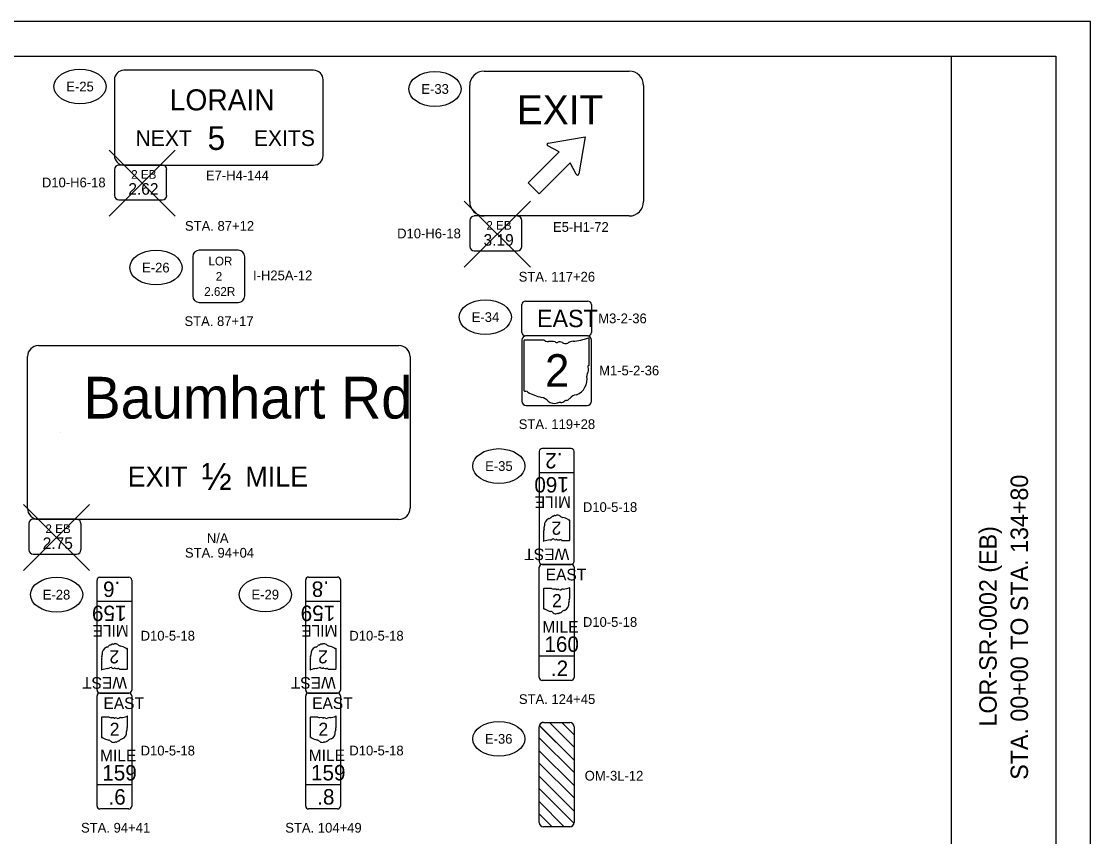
# Model space of a CAD drawing. Extents: x 0 to 34, y 0 to 22.
# Drawn here: x 18.63 to 34, y 10.28 to 22 of the extents above; entities that cross this region are included whole.
import ezdxf

# ---------------------------------------------------------------- set-up
doc = ezdxf.new("R2010")
doc.units = 0
for name, color, linetype in [('SH_Border', 7, 'Continuous'), ('SH_Cut_Line', 7, 'Continuous'), ('SH_Data', 7, 'Continuous'), ('SH_Text', 7, 'Continuous'), ('SN_P_Signs', 7, 'Continuous'), ('SN_X_Public', 7, 'Continuous')]:
    doc.layers.add(name, color=color, linetype=linetype)

msp = doc.modelspace()

# ---------------------------------------------------------------- linework, layer by layer
at = {"layer": 'SH_Border'}
msp.add_line((32, 0.5), (32, 21.5), dxfattribs=at)
msp.add_lwpolyline([(1.5, 21.5), (33.5, 21.5), (33.5, 0.5), (1.5, 0.5)], close=True, dxfattribs=at)
at = {"layer": 'SH_Cut_Line'}
msp.add_lwpolyline([(0, 0), (34, 0), (34, 22), (0, 22)], close=True, dxfattribs=at)
at = {"layer": 'SH_Text'}
for points in [[(18.878, 17.34), (24.058, 17.34)], [(18.718, 15), (18.718, 17.18)], [(24.218, 17.18), (24.218, 15)], [(26.533, 15.859), (26.117, 15.859)], [(26.075, 15.817), (26.075, 14.234)], [(26.575, 14.234), (26.575, 15.817)], [(24.058, 14.84), (18.878, 14.84)], [(26.075, 12.567), (26.075, 14.151)], [(26.117, 14.192), (26.533, 14.192)], [(26.117, 14.192), (26.533, 14.192)], [(26.575, 14.151), (26.575, 12.567)], [(26.533, 12.526), (26.117, 12.526)]]:
    msp.add_lwpolyline(points, dxfattribs=at)
for centre, radius, start, end in [((18.878, 17.18), 0.16, 90, 180), ((24.058, 17.18), 0.16, 0, 90), ((26.117, 15.817), 0.0417, 90, 180), ((26.533, 15.817), 0.0417, 0, 90), ((18.878, 15), 0.16, 180, 270), ((24.058, 15), 0.16, 270, 0), ((26.117, 14.234), 0.0417, 180, 270), ((26.117, 14.151), 0.0417, 90, 180), ((26.533, 14.234), 0.0417, 270, 360), ((26.533, 14.151), 0.0417, 0, 90), ((26.117, 12.567), 0.0417, 180, 270), ((26.533, 12.567), 0.0417, 270, 0)]:
    msp.add_arc(centre, radius, start, end, dxfattribs=at)
for centre in [(19.473, 21.063), (24.575, 21.028), (20.565, 18.46), (25.299, 17.748), (25.494, 15.607), (19.137, 13.758), (22.137, 13.759), (25.494, 11.685)]:
    msp.add_ellipse(centre, major_axis=(0.375, 0), ratio=0.666667, dxfattribs=at)
at = {"layer": 'SN_P_Signs'}
for p, q in [((26.202, 20.25), (26.733, 20.34)), ((26.36, 20.124), (26.196, 20.21)), ((25.916, 19.679), (26.36, 20.124)), ((26.518, 19.967), (26.073, 19.522)), ((26.604, 19.802), (26.518, 19.967)), ((26.073, 19.522), (25.916, 19.679)), ((26.605, 19.802), (26.604, 19.802)), ((25.825, 17.529), (25.825, 17.929)), ((25.875, 17.979), (26.775, 17.979)), ((26.825, 17.929), (26.825, 17.529)), ((25.855, 17.407), (25.855, 16.695)), ((26.139, 17.419), (25.865, 17.419)), ((26.775, 17.479), (25.875, 17.479)), ((26.793, 17.065), (26.793, 17.437)), ((26.793, 17.065), (26.793, 17.065)), ((19.199, 16.09), (19.199, 16.09)), ((26.075, 15.512), (26.575, 15.512)), ((26.512, 14.542), (26.512, 14.827)), ((26.137, 14.679), (26.137, 14.53)), ((26.137, 14.679), (26.137, 14.679)), ((26.325, 14.713), (26.325, 14.713)), ((26.399, 14.537), (26.509, 14.537)), ((26.137, 13.842), (26.137, 13.558)), ((26.251, 13.847), (26.141, 13.847)), ((26.512, 13.705), (26.512, 13.854)), ((26.512, 13.705), (26.512, 13.705)), ((19.718, 13.663), (20.218, 13.663)), ((22.718, 13.663), (23.218, 13.663)), ((26.325, 13.671), (26.325, 13.671)), ((20.156, 12.693), (20.156, 12.978)), ((23.156, 12.694), (23.156, 12.978)), ((19.781, 12.83), (19.781, 12.681)), ((19.781, 12.83), (19.781, 12.83)), ((19.968, 12.864), (19.968, 12.864)), ((22.781, 12.831), (22.781, 12.682)), ((22.781, 12.831), (22.781, 12.831)), ((22.968, 12.865), (22.968, 12.865)), ((26.575, 12.873), (26.075, 12.873)), ((20.042, 12.688), (20.152, 12.688)), ((23.042, 12.689), (23.152, 12.689)), ((19.781, 11.993), (19.781, 11.709)), ((19.894, 11.998), (19.784, 11.998)), ((20.156, 11.856), (20.156, 12.005)), ((22.781, 11.994), (22.781, 11.709)), ((22.894, 11.999), (22.784, 11.999)), ((23.156, 11.857), (23.156, 12.006)), ((20.156, 11.856), (20.156, 11.856)), ((23.156, 11.857), (23.156, 11.857)), ((26.575, 11.378), (26.075, 11.878)), ((26.575, 11.567), (26.22, 11.922)), ((26.575, 11.744), (26.397, 11.922)), ((19.968, 11.822), (19.968, 11.822)), ((22.968, 11.823), (22.968, 11.823)), ((26.575, 11.201), (26.075, 11.701)), ((26.575, 11.013), (26.075, 11.513)), ((26.575, 10.836), (26.075, 11.336)), ((26.575, 10.647), (26.075, 11.147)), ((20.218, 11.024), (19.718, 11.024)), ((23.218, 11.024), (22.718, 11.024)), ((26.575, 10.47), (26.075, 10.97)), ((26.435, 10.422), (26.075, 10.782)), ((26.258, 10.422), (26.075, 10.605))]:
    msp.add_line(p, q, dxfattribs=at)
for points in [[(22.832, 21.298), (20.104, 21.298)], [(25.283, 21.285), (27.367, 21.285)], [(19.968, 21.161), (19.968, 20.07)], [(22.968, 20.07), (22.968, 21.161)], [(25.075, 19.41), (25.075, 21.077)], [(27.575, 21.077), (27.575, 19.41)], [(26.733, 20.34), (26.733, 20.34), (26.643, 19.808)], [(19.969, 19.872), (19.969, 19.497)], [(20.657, 19.935), (20.032, 19.935)], [(20.104, 19.934), (22.832, 19.934)], [(20.719, 19.497), (20.719, 19.872)], [(20.032, 19.435), (20.657, 19.435)], [(25.075, 19.139), (25.075, 18.764)], [(25.763, 19.202), (25.138, 19.202)], [(27.367, 19.202), (25.283, 19.202)], [(25.825, 18.764), (25.825, 19.139)], [(21.093, 18.616), (21.093, 18.054)], [(21.749, 18.71), (21.187, 18.71)], [(21.843, 18.054), (21.843, 18.616)], [(25.138, 18.702), (25.763, 18.702)], [(21.187, 17.96), (21.749, 17.96)], [(25.825, 17.416), (25.825, 16.541)], [(26.762, 17.479), (25.887, 17.479)], [(26.825, 16.541), (26.825, 17.416)], [(25.887, 16.479), (26.762, 16.479)], [(18.738, 14.779), (18.738, 14.404)], [(19.425, 14.841), (18.8, 14.841)], [(19.488, 14.404), (19.488, 14.779)], [(18.8, 14.341), (19.425, 14.341)], [(26.533, 14.192), (26.117, 14.192)], [(19.76, 14.01), (20.176, 14.01)], [(22.76, 14.01), (23.176, 14.01)], [(19.718, 12.385), (19.718, 13.968)], [(20.218, 13.968), (20.218, 12.385)], [(22.718, 12.385), (22.718, 13.969)], [(23.218, 13.969), (23.218, 12.385)], [(19.718, 10.718), (19.718, 12.302)], [(20.176, 12.343), (19.76, 12.343)], [(19.76, 12.343), (20.176, 12.343)], [(20.218, 12.302), (20.218, 10.718)], [(22.718, 10.719), (22.718, 12.302)], [(23.176, 12.344), (22.76, 12.344)], [(22.76, 12.344), (23.176, 12.344)], [(23.218, 12.302), (23.218, 10.719)], [(26.075, 10.484), (26.075, 11.859)], [(26.137, 11.922), (26.22, 11.922), (26.575, 11.567), (26.575, 11.378), (26.077, 11.876)], [(26.137, 11.922), (26.512, 11.922)], [(26.397, 11.922), (26.512, 11.922)], [(26.575, 11.859), (26.575, 11.744), (26.397, 11.922)], [(26.575, 11.859), (26.575, 10.484)], [(26.075, 11.513), (26.075, 11.701), (26.575, 11.201), (26.575, 11.013), (26.075, 11.513)], [(26.075, 11.147), (26.075, 11.336), (26.575, 10.836), (26.575, 10.647), (26.075, 11.147)], [(26.512, 10.422), (26.435, 10.422), (26.075, 10.782), (26.075, 10.97), (26.574, 10.472)], [(20.176, 10.677), (19.76, 10.677)], [(23.176, 10.677), (22.76, 10.677)], [(26.075, 10.484), (26.075, 10.605), (26.258, 10.422)], [(26.512, 10.422), (26.137, 10.422)], [(26.258, 10.422), (26.137, 10.422)]]:
    msp.add_lwpolyline(points, dxfattribs=at)
for centre, radius, start, end in [((20.104, 21.161), 0.136, 90, 180), ((22.832, 21.161), 0.136, 0, 90), ((25.283, 21.077), 0.208, 90, 180), ((27.367, 21.077), 0.208, 0, 90), ((26.206, 20.229), 0.0208, 99.6076, 242.1805), ((20.104, 20.07), 0.136, 180, 270), ((22.832, 20.07), 0.136, 270, 360), ((20.032, 19.872), 0.0625, 90, 180), ((20.657, 19.872), 0.0625, 0, 90), ((26.623, 19.811), 0.0208, 207.8195, 350.3924), ((20.032, 19.497), 0.0625, 180, 270), ((20.657, 19.497), 0.0625, 270, 0), ((25.283, 19.41), 0.208, 180, 270), ((27.367, 19.41), 0.208, 270, 0), ((25.138, 19.139), 0.0625, 90, 180), ((25.763, 19.139), 0.0625, 0, 90), ((25.138, 18.764), 0.0625, 180, 270), ((25.763, 18.764), 0.0625, 270, 0), ((21.187, 18.616), 0.0938, 90, 180), ((21.749, 18.616), 0.0938, 0, 90), ((21.187, 18.054), 0.0938, 180, 270), ((21.749, 18.054), 0.0938, 270, 0), ((25.875, 17.929), 0.05, 90, 180), ((26.775, 17.929), 0.05, 0, 90), ((25.875, 17.529), 0.05, 180, 270), ((26.775, 17.529), 0.05, 270, 0), ((25.887, 17.416), 0.0625, 90, 180), ((25.866, 17.408), 0.0109, 98.1301, 188.1301), ((26.205, 17.502), 0.105, 231.6195, 271.1119), ((26.24, 17.02), 0.378, 80.4867, 94.9883), ((26.325, 17.412), 0.0304, 219.7921, 297.1024), ((26.37, 17.33), 0.0632, 54.4667, 119.1411), ((26.452, 17.443), 0.076, 233.8562, 294.8282), ((26.586, 17.202), 0.2, 97.3462, 120.7689), ((26.459, 18.389), 0.994, 275.8445, 288.9065), ((26.762, 17.416), 0.0625, 0, 90), ((26.783, 17.438), 0.0104, 351.8621, 97.738), ((26.782, 17.063), 0.0112, 289.6038, 7.7341), ((26.83, 16.909), 0.0705, 136.8065, 186.9296), ((26.79, 17.037), 0.0162, 107.944, 210.337), ((26.688, 16.99), 0.097, 340.033, 23.6496), ((26.515, 16.861), 0.249, 292.3089, 8.9858), ((25.866, 16.694), 0.011, 171.9584, 258.3066), ((25.868, 16.767), 0.0836, 267.339, 280.6039), ((25.885, 16.654), 0.0302, 29.7484, 93.2717), ((26.266, 17.294), 0.718, 240.4129, 257.1985), ((26.62, 16.496), 0.136, 94.4031, 142.5768), ((25.887, 16.541), 0.0625, 180, 270), ((26.052, 16.376), 0.225, 47.1842, 75.836), ((26.295, 16.651), 0.143, 230.7004, 286.2918), ((26.377, 16.405), 0.117, 85.6951, 111.2099), ((26.387, 16.597), 0.0759, 268.777, 315.5493), ((26.456, 16.529), 0.0214, 65.7517, 132.6484), ((26.447, 16.626), 0.0803, 282.8732, 323.2771), ((26.762, 16.541), 0.0625, 270, 0), ((18.8, 14.779), 0.0625, 90, 180), ((19.425, 14.779), 0.0625, 0, 90), ((26.249, 14.761), 0.0995, 112.3089, 188.9858), ((26.207, 14.907), 0.0545, 274.4031, 322.5768), ((26.276, 14.855), 0.0321, 102.8732, 143.2771), ((26.272, 14.894), 0.00855, 245.7517, 312.6484), ((26.3, 14.866), 0.0304, 88.777, 135.5493), ((26.304, 14.943), 0.0468, 265.6951, 291.2099), ((26.337, 14.845), 0.057, 50.7004, 106.2918), ((26.434, 14.955), 0.0899, 227.1842, 255.836), ((26.348, 14.588), 0.287, 60.4129, 77.1985), ((26.501, 14.843), 0.0121, 209.7484, 273.2717), ((26.507, 14.798), 0.0334, 87.339, 100.6039), ((26.508, 14.828), 0.00438, 351.9584, 78.3066), ((26.142, 14.68), 0.00447, 109.6038, 187.7341), ((26.138, 14.69), 0.00646, 287.944, 30.337), ((26.179, 14.709), 0.0388, 160.033, 203.6496), ((26.122, 14.742), 0.0282, 316.8065, 6.9296), ((26.142, 14.53), 0.00417, 171.8621, 277.738), ((26.271, 14.149), 0.398, 95.8445, 108.9065), ((26.22, 14.624), 0.08, 277.3462, 300.7689), ((26.274, 14.528), 0.0304, 53.8562, 114.8282), ((26.307, 14.573), 0.0253, 234.4667, 299.1411), ((26.324, 14.54), 0.0122, 39.7921, 117.1024), ((26.359, 14.697), 0.151, 260.4867, 274.9883), ((26.373, 14.504), 0.0421, 51.6195, 91.1119), ((26.508, 14.542), 0.00434, 278.1301, 8.1301), ((18.8, 14.404), 0.0625, 180, 270), ((19.425, 14.404), 0.0625, 270, 0), ((19.76, 13.968), 0.0417, 90, 180), ((20.176, 13.968), 0.0417, 0, 90), ((22.76, 13.969), 0.0417, 90, 180), ((23.176, 13.969), 0.0417, 0, 90), ((26.142, 13.843), 0.00434, 98.1301, 188.1301), ((26.277, 13.88), 0.0421, 231.6195, 271.1119), ((26.291, 13.687), 0.151, 80.4867, 94.9883), ((26.325, 13.844), 0.0122, 219.7921, 297.1024), ((26.343, 13.811), 0.0253, 54.4667, 119.1411), ((26.43, 13.76), 0.08, 97.3462, 120.7689), ((26.379, 14.235), 0.398, 275.8445, 288.9065), ((26.508, 13.855), 0.00417, 351.8621, 97.738), ((26.376, 13.857), 0.0304, 233.8562, 294.8282), ((26.511, 13.694), 0.00646, 107.944, 210.337), ((26.47, 13.676), 0.0388, 340.033, 23.6496), ((26.508, 13.705), 0.00447, 289.6038, 7.7341), ((26.142, 13.557), 0.00438, 171.9584, 258.3066), ((26.142, 13.586), 0.0334, 267.339, 280.6039), ((26.149, 13.541), 0.0121, 29.7484, 93.2717), ((26.302, 13.797), 0.287, 240.4129, 257.1985), ((26.443, 13.478), 0.0545, 94.4031, 142.5768), ((26.401, 13.624), 0.0995, 292.3089, 8.9858), ((26.527, 13.643), 0.0282, 136.8065, 186.9296), ((26.216, 13.43), 0.0899, 47.1842, 75.836), ((26.313, 13.54), 0.057, 230.7004, 286.2918), ((26.346, 13.441), 0.0468, 85.6951, 111.2099), ((26.35, 13.518), 0.0304, 268.777, 315.5493), ((26.378, 13.491), 0.00855, 65.7517, 132.6484), ((26.374, 13.53), 0.0321, 282.8732, 323.2771), ((19.892, 12.912), 0.0995, 112.3089, 188.9858), ((19.85, 13.058), 0.0545, 274.4031, 322.5768), ((19.919, 13.006), 0.0321, 102.8732, 143.2771), ((19.915, 13.045), 0.00855, 245.7517, 312.6484), ((19.943, 13.017), 0.0304, 88.777, 135.5493), ((19.947, 13.094), 0.0468, 265.6951, 291.2099), ((19.98, 12.996), 0.057, 50.7004, 106.2918), ((20.077, 13.106), 0.0899, 227.1842, 255.836), ((19.991, 12.739), 0.287, 60.4129, 77.1985), ((20.144, 12.994), 0.0121, 209.7484, 273.2717), ((20.151, 12.949), 0.0334, 87.339, 100.6039), ((20.151, 12.979), 0.00438, 351.9584, 78.3066), ((22.892, 12.912), 0.0995, 112.3089, 188.9858), ((22.85, 13.058), 0.0545, 274.4031, 322.5768), ((22.919, 13.006), 0.0321, 102.8732, 143.2771), ((22.915, 13.045), 0.00855, 245.7517, 312.6484), ((22.943, 13.017), 0.0304, 88.777, 135.5493), ((22.947, 13.095), 0.0468, 265.6951, 291.2099), ((22.98, 12.996), 0.057, 50.7004, 106.2918), ((23.077, 13.106), 0.0899, 227.1842, 255.836), ((22.991, 12.739), 0.287, 60.4129, 77.1985), ((23.144, 12.995), 0.0121, 209.7484, 273.2717), ((23.151, 12.95), 0.0334, 87.339, 100.6039), ((23.151, 12.979), 0.00438, 351.9584, 78.3066), ((19.785, 12.831), 0.00447, 109.6038, 187.7341), ((19.823, 12.86), 0.0388, 160.033, 203.6496), ((19.782, 12.841), 0.00646, 287.944, 30.337), ((19.766, 12.893), 0.0282, 316.8065, 6.9296), ((22.785, 12.831), 0.00447, 109.6038, 187.7341), ((22.823, 12.86), 0.0388, 160.033, 203.6496), ((22.782, 12.842), 0.00646, 287.944, 30.337), ((22.766, 12.893), 0.0282, 316.8065, 6.9296), ((19.785, 12.681), 0.00417, 171.8621, 277.738), ((19.914, 12.3), 0.398, 95.8445, 108.9065), ((19.863, 12.775), 0.08, 277.3462, 300.7689), ((19.917, 12.679), 0.0304, 53.8562, 114.8282), ((19.95, 12.724), 0.0253, 234.4667, 299.1411), ((19.968, 12.691), 0.0122, 39.7921, 117.1024), ((20.002, 12.848), 0.151, 260.4867, 274.9883), ((20.016, 12.655), 0.0421, 51.6195, 91.1119), ((20.151, 12.693), 0.00434, 278.1301, 8.1301), ((22.785, 12.681), 0.00417, 171.8621, 277.738), ((22.914, 12.301), 0.398, 95.8445, 108.9065), ((22.863, 12.776), 0.08, 277.3462, 300.7689), ((22.917, 12.679), 0.0304, 53.8562, 114.8282), ((22.95, 12.725), 0.0253, 234.4667, 299.1411), ((22.968, 12.692), 0.0122, 39.7921, 117.1024), ((23.002, 12.849), 0.151, 260.4867, 274.9883), ((23.016, 12.656), 0.0421, 51.6195, 91.1119), ((23.151, 12.693), 0.00434, 278.1301, 8.1301), ((19.76, 12.385), 0.0417, 180, 270), ((19.76, 12.302), 0.0417, 90, 180), ((20.176, 12.385), 0.0417, 270, 360), ((20.176, 12.302), 0.0417, 0, 90), ((22.76, 12.385), 0.0417, 180, 270), ((22.76, 12.302), 0.0417, 90, 180), ((23.176, 12.385), 0.0417, 270, 360), ((23.176, 12.302), 0.0417, 0, 90), ((19.785, 11.994), 0.00434, 98.1301, 188.1301), ((19.92, 12.031), 0.0421, 231.6195, 271.1119), ((19.934, 11.838), 0.151, 80.4867, 94.9883), ((20.073, 11.911), 0.08, 97.3462, 120.7689), ((20.022, 12.386), 0.398, 275.8445, 288.9065), ((20.151, 12.006), 0.00417, 351.8621, 97.738), ((22.785, 11.994), 0.00434, 98.1301, 188.1301), ((22.92, 12.032), 0.0421, 231.6195, 271.1119), ((22.934, 11.839), 0.151, 80.4867, 94.9883), ((22.969, 11.996), 0.0122, 219.7921, 297.1024), ((22.986, 11.963), 0.0253, 54.4667, 119.1411), ((23.073, 11.912), 0.08, 97.3462, 120.7689), ((23.022, 12.387), 0.398, 275.8445, 288.9065), ((23.151, 12.006), 0.00417, 351.8621, 97.738), ((19.969, 11.995), 0.0122, 219.7921, 297.1024), ((19.986, 11.962), 0.0253, 54.4667, 119.1411), ((20.019, 12.008), 0.0304, 233.8562, 294.8282), ((20.155, 11.845), 0.00646, 107.944, 210.337), ((20.114, 11.827), 0.0388, 340.033, 23.6496), ((20.151, 11.856), 0.00447, 289.6038, 7.7341), ((23.019, 12.008), 0.0304, 233.8562, 294.8282), ((23.155, 11.846), 0.00646, 107.944, 210.337), ((23.114, 11.827), 0.0388, 340.033, 23.6496), ((23.151, 11.856), 0.00447, 289.6038, 7.7341), ((26.137, 11.859), 0.0625, 90, 180), ((26.137, 11.859), 0.0625, 90, 164.7237), ((26.512, 11.859), 0.0625, 0, 90), ((26.512, 11.859), 0.0625, 0, 90), ((19.785, 11.708), 0.00438, 171.9584, 258.3066), ((19.786, 11.737), 0.0334, 267.339, 280.6039), ((19.792, 11.692), 0.0121, 29.7484, 93.2717), ((19.945, 11.948), 0.287, 240.4129, 257.1985), ((20.086, 11.629), 0.0545, 94.4031, 142.5768), ((20.044, 11.775), 0.0995, 292.3089, 8.9858), ((20.171, 11.794), 0.0282, 136.8065, 186.9296), ((22.785, 11.708), 0.00438, 171.9584, 258.3066), ((22.786, 11.738), 0.0334, 267.339, 280.6039), ((22.792, 11.693), 0.0121, 29.7484, 93.2717), ((22.945, 11.948), 0.287, 240.4129, 257.1985), ((23.086, 11.629), 0.0545, 94.4031, 142.5768), ((23.044, 11.775), 0.0995, 292.3089, 8.9858), ((23.171, 11.794), 0.0282, 136.8065, 186.9296), ((19.859, 11.581), 0.0899, 47.1842, 75.836), ((19.956, 11.691), 0.057, 230.7004, 286.2918), ((19.989, 11.592), 0.0468, 85.6951, 111.2099), ((19.993, 11.67), 0.0304, 268.777, 315.5493), ((20.021, 11.642), 0.00855, 65.7517, 132.6484), ((20.017, 11.681), 0.0321, 282.8732, 323.2771), ((22.859, 11.581), 0.0899, 47.1842, 75.836), ((22.956, 11.691), 0.057, 230.7004, 286.2918), ((22.989, 11.593), 0.0468, 85.6951, 111.2099), ((22.993, 11.67), 0.0304, 268.777, 315.5493), ((23.021, 11.642), 0.00855, 65.7517, 132.6484), ((23.017, 11.681), 0.0321, 282.8732, 323.2771), ((19.76, 10.718), 0.0417, 180, 270), ((20.176, 10.718), 0.0417, 270, 0), ((22.76, 10.719), 0.0417, 180, 270), ((23.176, 10.719), 0.0417, 270, 0), ((26.137, 10.484), 0.0625, 180, 270), ((26.137, 10.484), 0.0625, 180, 270), ((26.512, 10.484), 0.0625, 270, 360), ((26.512, 10.484), 0.0625, 270, 348.268)]:
    msp.add_arc(centre, radius, start, end, dxfattribs=at)
at = {"layer": 'SN_X_Public'}
for p, q in [((19.891, 19.198), (20.841, 20.148)), ((19.891, 20.148), (20.841, 19.198)), ((24.997, 18.465), (25.947, 19.415)), ((24.997, 19.415), (25.947, 18.465)), ((18.66, 14.105), (19.61, 15.055)), ((18.66, 15.055), (19.61, 14.105))]:
    msp.add_line(p, q, dxfattribs=at)

# ---------------------------------------------------------------- texts
at = {"layer": 'SH_Data'}
for s, p in [('STA. 00+00 TO STA. 134+80', (33.1, 11.097)), ('LOR-SR-0002 (EB)', (32.65, 11.863))]:
    msp.add_text(s, height=0.25, rotation=90, dxfattribs=at).set_placement(p)
at = {"layer": 'SH_Text'}
for s, p in [('E-25', (19.276, 20.993)), ('E-33', (24.38, 20.958)), ('E7-H4-144', (21.283, 19.716)), ('D10-H6-18', (18.926, 19.614)), ('STA. 87+12', (20.982, 18.99)), ('E5-H1-72', (26.272, 18.974)), ('D10-H6-18', (24.032, 18.881)), ('E-26', (20.366, 18.39)), ('I-H25A-12', (21.96, 18.278)), ('STA. 117+26', (25.779, 18.259)), ('STA. 87+17', (20.975, 17.62)), ('E-34', (25.104, 17.678)), ('M3-2-36', (26.923, 17.66)), ('M1-5-2-36', (26.935, 16.911)), ('STA. 119+28', (25.78, 16.139)), ('E-35', (25.297, 15.537)), ('D10-5-18', (26.702, 14.947)), ('N/A', (21.297, 14.5)), ('STA. 94+04', (20.982, 14.29)), ('E-28', (18.938, 13.688)), ('E-29', (21.939, 13.689)), ('D10-5-18', (26.702, 13.295)), ('D10-5-18', (20.345, 13.098)), ('D10-5-18', (23.345, 13.098)), ('STA. 124+45', (25.782, 12.186)), ('E-36', (25.294, 11.615)), ('D10-5-18', (20.345, 11.446)), ('D10-5-18', (23.345, 11.447)), ('OM-3L-12', (26.728, 11.085)), ('STA. 94+41', (19.488, 10.337)), ('STA. 104+49', (22.424, 10.337))]:
    msp.add_text(s, height=0.14, dxfattribs=at).set_placement(p)
at = {"layer": 'SN_P_Signs'}
for s, height, p in [('LORAIN', 0.303, (20.763, 20.72)), ('EXIT', 0.4167, (25.754, 20.521)), ('5', 0.341, (21.307, 20.152)), ('NEXT', 0.2273, (20.271, 20.208)), ('EXITS', 0.2273, (21.972, 20.208)), ('2 EB', 0.125, (20.209, 19.737)), ('2.62', 0.1667, (20.168, 19.508)), ('2 EB', 0.125, (25.315, 19.004)), ('3.19', 0.1667, (25.274, 18.775)), ('LOR', 0.125, (21.32, 18.491)), ('2', 0.125, (21.425, 18.272)), ('2.62R', 0.125, (21.259, 18.054)), ('EAST', 0.25, (26.043, 17.604)), ('2', 0.469, (26.158, 16.746)), ('Baumhart Rd', 0.60001, (19.523, 16.29)), ('EXIT', 0.2892, (20.159, 15.311)), ('½', 0.386, (21.224, 15.263)), ('MILE', 0.2892, (21.85, 15.311)), ('2 EB', 0.125, (18.977, 14.643)), ('2.75', 0.1667, (18.937, 14.414)), ('EAST', 0.1667, (26.168, 13.963)), ('2', 0.188, (26.258, 13.578)), ('MILE', 0.1667, (26.119, 13.213)), ('160', 0.2222, (26.149, 12.935)), ('.2', 0.2222, (26.242, 12.588)), ('EAST', 0.1667, (19.811, 12.114)), ('EAST', 0.1667, (22.811, 12.115)), ('2', 0.188, (19.901, 11.729)), ('2', 0.188, (22.901, 11.729)), ('MILE', 0.1667, (19.762, 11.364)), ('MILE', 0.1667, (22.762, 11.365)), ('159', 0.2222, (19.794, 11.086)), ('159', 0.2222, (22.794, 11.087)), ('.6', 0.2222, (19.883, 10.739)), ('.8', 0.2222, (22.883, 10.74))]:
    msp.add_text(s, height=height, dxfattribs=at).set_placement(p)
for s, height, p in [('.2', 0.2222, (26.408, 15.796)), ('160', 0.2222, (26.5, 15.449)), ('MILE', 0.1667, (26.531, 15.171)), ('2', 0.188, (26.392, 14.807)), ('WEST', 0.1667, (26.506, 14.421)), ('.6', 0.2222, (20.053, 13.947)), ('.8', 0.2222, (23.053, 13.948)), ('159', 0.2222, (20.142, 13.6)), ('159', 0.2222, (23.142, 13.601)), ('MILE', 0.1667, (20.174, 13.322)), ('MILE', 0.1667, (23.174, 13.323)), ('2', 0.188, (20.035, 12.958)), ('2', 0.188, (23.035, 12.958)), ('WEST', 0.1667, (20.149, 12.572)), ('WEST', 0.1667, (23.149, 12.573))]:
    msp.add_text(s, height=height, rotation=180, dxfattribs=at).set_placement(p)

doc.saveas('drawing.dxf')
